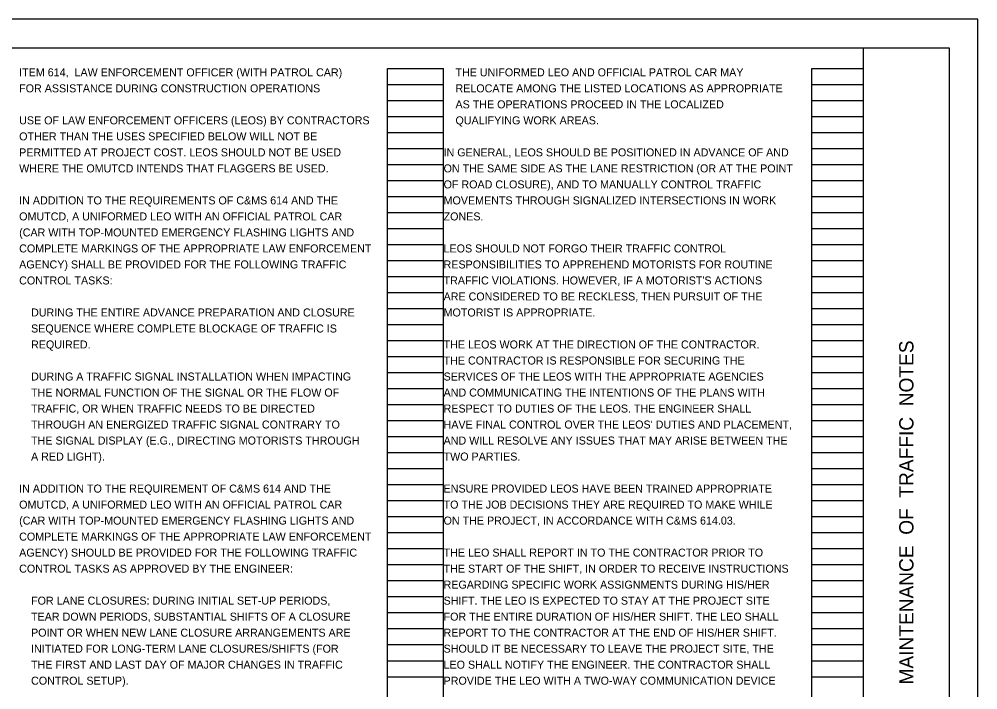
# Model space of a CAD drawing. Extents: x 0 to 34, y 0 to 22.
# Drawn here: x 17.24 to 34, y 10.27 to 22 of the extents above; entities that cross this region are included whole.
import ezdxf

# ---------------------------------------------------------------- set-up
doc = ezdxf.new("R2010")
doc.units = 0
for name, color, linetype in [('SH_Border', 7, 'Continuous'), ('SH_Cut_Line', 7, 'Continuous'), ('SH_Data', 7, 'Continuous'), ('SH_Text', 7, 'Continuous')]:
    doc.layers.add(name, color=color, linetype=linetype)

msp = doc.modelspace()

# ---------------------------------------------------------------- linework, layer by layer
at = {"layer": 'SH_Border'}
msp.add_line((32, 0.5), (32, 21.5), dxfattribs=at)
msp.add_lwpolyline([(1.5, 21.5), (33.5, 21.5), (33.5, 0.5), (1.5, 0.5)], close=True, dxfattribs=at)
at = {"layer": 'SH_Cut_Line'}
msp.add_lwpolyline([(0, 0), (34, 0), (34, 22), (0, 22)], close=True, dxfattribs=at)
at = {"layer": 'SH_Data'}
for p, q in [((23.68, 0.98), (23.68, 21.14)), ((23.68, 21.14), (24.66, 21.14)), ((24.66, 0.98), (24.66, 21.14)), ((31.1, 0.98), (31.1, 21.14)), ((31.1, 21.14), (32, 21.14)), ((32, 0.98), (32, 21.14)), ((23.68, 20.86), (24.66, 20.86)), ((31.1, 20.86), (32, 20.86)), ((23.68, 20.58), (24.66, 20.58)), ((31.1, 20.58), (32, 20.58)), ((23.68, 20.3), (24.66, 20.3)), ((31.1, 20.3), (32, 20.3)), ((23.68, 20.02), (24.66, 20.02)), ((31.1, 20.02), (32, 20.02)), ((23.68, 19.74), (24.66, 19.74)), ((31.1, 19.74), (32, 19.74)), ((23.68, 19.46), (24.66, 19.46)), ((31.1, 19.46), (32, 19.46)), ((23.68, 19.18), (24.66, 19.18)), ((31.1, 19.18), (32, 19.18)), ((23.68, 18.9), (24.66, 18.9)), ((31.1, 18.9), (32, 18.9)), ((23.68, 18.62), (24.66, 18.62)), ((31.1, 18.62), (32, 18.62)), ((23.68, 18.34), (24.66, 18.34)), ((31.1, 18.34), (32, 18.34)), ((23.68, 18.06), (24.66, 18.06)), ((31.1, 18.06), (32, 18.06)), ((23.68, 17.78), (24.66, 17.78)), ((31.1, 17.78), (32, 17.78)), ((23.68, 17.5), (24.66, 17.5)), ((31.1, 17.5), (32, 17.5)), ((23.68, 17.22), (24.66, 17.22)), ((31.1, 17.22), (32, 17.22)), ((23.68, 16.94), (24.66, 16.94)), ((31.1, 16.94), (32, 16.94)), ((23.68, 16.66), (24.66, 16.66)), ((31.1, 16.66), (32, 16.66)), ((23.68, 16.38), (24.66, 16.38)), ((31.1, 16.38), (32, 16.38)), ((23.68, 16.1), (24.66, 16.1)), ((31.1, 16.1), (32, 16.1)), ((23.68, 15.82), (24.66, 15.82)), ((31.1, 15.82), (32, 15.82)), ((23.68, 15.54), (24.66, 15.54)), ((31.1, 15.54), (32, 15.54)), ((23.68, 15.26), (24.66, 15.26)), ((31.1, 15.26), (32, 15.26)), ((23.68, 14.98), (24.66, 14.98)), ((31.1, 14.98), (32, 14.98)), ((23.68, 14.7), (24.66, 14.7)), ((31.1, 14.7), (32, 14.7)), ((23.68, 14.42), (24.66, 14.42)), ((31.1, 14.42), (32, 14.42)), ((23.68, 14.14), (24.66, 14.14)), ((31.1, 14.14), (32, 14.14)), ((23.68, 13.86), (24.66, 13.86)), ((31.1, 13.86), (32, 13.86)), ((23.68, 13.58), (24.66, 13.58)), ((31.1, 13.58), (32, 13.58)), ((23.68, 13.3), (24.66, 13.3)), ((31.1, 13.3), (32, 13.3)), ((23.68, 13.02), (24.66, 13.02)), ((31.1, 13.02), (32, 13.02)), ((23.68, 12.74), (24.66, 12.74)), ((31.1, 12.74), (32, 12.74)), ((23.68, 12.46), (24.66, 12.46)), ((31.1, 12.46), (32, 12.46)), ((23.68, 12.18), (24.66, 12.18)), ((31.1, 12.18), (32, 12.18)), ((23.68, 11.9), (24.66, 11.9)), ((31.1, 11.9), (32, 11.9)), ((23.68, 11.62), (24.66, 11.62)), ((31.1, 11.62), (32, 11.62)), ((23.68, 11.34), (24.66, 11.34)), ((31.1, 11.34), (32, 11.34)), ((23.68, 11.06), (24.66, 11.06)), ((31.1, 11.06), (32, 11.06)), ((23.68, 10.78), (24.66, 10.78)), ((31.1, 10.78), (32, 10.78)), ((23.68, 10.5), (24.66, 10.5)), ((31.1, 10.5), (32, 10.5))]:
    msp.add_line(p, q, dxfattribs=at)

# ---------------------------------------------------------------- texts
msp.add_text('MAINTENANCE  OF  TRAFFIC  NOTES', height=0.25, rotation=90, dxfattribs=at).set_placement((32.875, 10.363))
at = {"layer": 'SH_Text'}
for s, p in [('ITEM 614,  LAW ENFORCEMENT OFFICER (WITH PATROL CAR)', (17.24, 21)), ('    THE UNIFORMED LEO AND OFFICIAL PATROL CAR MAY', (24.66, 21)), ('FOR ASSISTANCE DURING CONSTRUCTION OPERATIONS', (17.24, 20.72)), ('    RELOCATE AMONG THE LISTED LOCATIONS AS APPROPRIATE', (24.66, 20.72)), ('    AS THE OPERATIONS PROCEED IN THE LOCALIZED', (24.66, 20.44)), ('USE OF LAW ENFORCEMENT OFFICERS (LEOS) BY CONTRACTORS', (17.24, 20.16)), ('    QUALIFYING WORK AREAS.', (24.66, 20.16)), ('OTHER THAN THE USES SPECIFIED BELOW WILL NOT BE', (17.24, 19.88)), ('PERMITTED AT PROJECT COST. LEOS SHOULD NOT BE USED', (17.24, 19.6)), ('IN GENERAL, LEOS SHOULD BE POSITIONED IN ADVANCE OF AND', (24.66, 19.6)), ('WHERE THE OMUTCD INTENDS THAT FLAGGERS BE USED.', (17.24, 19.32)), ('ON THE SAME SIDE AS THE LANE RESTRICTION (OR AT THE POINT', (24.66, 19.32)), ('OF ROAD CLOSURE), AND TO MANUALLY CONTROL TRAFFIC', (24.66, 19.04)), ('IN ADDITION TO THE REQUIREMENTS OF C&MS 614 AND THE', (17.24, 18.76)), ('MOVEMENTS THROUGH SIGNALIZED INTERSECTIONS IN WORK', (24.66, 18.76)), ('OMUTCD, A UNIFORMED LEO WITH AN OFFICIAL PATROL CAR', (17.24, 18.48)), ('ZONES.', (24.66, 18.48)), ('(CAR WITH TOP-MOUNTED EMERGENCY FLASHING LIGHTS AND', (17.24, 18.2)), ('COMPLETE MARKINGS OF THE APPROPRIATE LAW ENFORCEMENT', (17.24, 17.92)), ('LEOS SHOULD NOT FORGO THEIR TRAFFIC CONTROL', (24.66, 17.92)), ('AGENCY) SHALL BE PROVIDED FOR THE FOLLOWING TRAFFIC', (17.24, 17.64)), ('RESPONSIBILITIES TO APPREHEND MOTORISTS FOR ROUTINE', (24.66, 17.64)), ('CONTROL TASKS:', (17.24, 17.36)), ("TRAFFIC VIOLATIONS. HOWEVER, IF A MOTORIST'S ACTIONS", (24.66, 17.36)), ('ARE CONSIDERED TO BE RECKLESS, THEN PURSUIT OF THE', (24.66, 17.08)), ('    DURING THE ENTIRE ADVANCE PREPARATION AND CLOSURE', (17.24, 16.8)), ('MOTORIST IS APPROPRIATE.', (24.66, 16.8)), ('    SEQUENCE WHERE COMPLETE BLOCKAGE OF TRAFFIC IS', (17.24, 16.52)), ('    REQUIRED.', (17.24, 16.24)), ('THE LEOS WORK AT THE DIRECTION OF THE CONTRACTOR.', (24.66, 16.24)), ('THE CONTRACTOR IS RESPONSIBLE FOR SECURING THE', (24.66, 15.96)), ('    DURING A TRAFFIC SIGNAL INSTALLATION WHEN IMPACTING', (17.24, 15.68)), ('SERVICES OF THE LEOS WITH THE APPROPRIATE AGENCIES', (24.66, 15.68)), ('    THE NORMAL FUNCTION OF THE SIGNAL OR THE FLOW OF', (17.24, 15.4)), ('AND COMMUNICATING THE INTENTIONS OF THE PLANS WITH', (24.66, 15.4)), ('    TRAFFIC, OR WHEN TRAFFIC NEEDS TO BE DIRECTED', (17.24, 15.12)), ('RESPECT TO DUTIES OF THE LEOS. THE ENGINEER SHALL', (24.66, 15.12)), ('    THROUGH AN ENERGIZED TRAFFIC SIGNAL CONTRARY TO', (17.24, 14.84)), ("HAVE FINAL CONTROL OVER THE LEOS' DUTIES AND PLACEMENT,", (24.66, 14.84)), ('    THE SIGNAL DISPLAY (E.G., DIRECTING MOTORISTS THROUGH', (17.24, 14.56)), ('AND WILL RESOLVE ANY ISSUES THAT MAY ARISE BETWEEN THE', (24.66, 14.56)), ('    A RED LIGHT).', (17.24, 14.28)), ('TWO PARTIES.', (24.66, 14.28)), ('IN ADDITION TO THE REQUIREMENT OF C&MS 614 AND THE', (17.24, 13.72)), ('ENSURE PROVIDED LEOS HAVE BEEN TRAINED APPROPRIATE', (24.66, 13.72)), ('OMUTCD, A UNIFORMED LEO WITH AN OFFICIAL PATROL CAR', (17.24, 13.44)), ('TO THE JOB DECISIONS THEY ARE REQUIRED TO MAKE WHILE', (24.66, 13.44)), ('(CAR WITH TOP-MOUNTED EMERGENCY FLASHING LIGHTS AND', (17.24, 13.16)), ('ON THE PROJECT, IN ACCORDANCE WITH C&MS 614.03.', (24.66, 13.16)), ('COMPLETE MARKINGS OF THE APPROPRIATE LAW ENFORCEMENT', (17.24, 12.88)), ('AGENCY) SHOULD BE PROVIDED FOR THE FOLLOWING TRAFFIC', (17.24, 12.6)), ('THE LEO SHALL REPORT IN TO THE CONTRACTOR PRIOR TO', (24.66, 12.6)), ('CONTROL TASKS AS APPROVED BY THE ENGINEER:', (17.24, 12.32)), ('THE START OF THE SHIFT, IN ORDER TO RECEIVE INSTRUCTIONS', (24.66, 12.32)), ('REGARDING SPECIFIC WORK ASSIGNMENTS DURING HIS/HER', (24.66, 12.04)), ('    FOR LANE CLOSURES: DURING INITIAL SET-UP PERIODS,', (17.24, 11.76)), ('SHIFT. THE LEO IS EXPECTED TO STAY AT THE PROJECT SITE', (24.66, 11.76)), ('    TEAR DOWN PERIODS, SUBSTANTIAL SHIFTS OF A CLOSURE', (17.24, 11.48)), ('FOR THE ENTIRE DURATION OF HIS/HER SHIFT. THE LEO SHALL', (24.66, 11.48)), ('    POINT OR WHEN NEW LANE CLOSURE ARRANGEMENTS ARE', (17.24, 11.2)), ('REPORT TO THE CONTRACTOR AT THE END OF HIS/HER SHIFT.', (24.66, 11.2)), ('    INITIATED FOR LONG-TERM LANE CLOSURES/SHIFTS (FOR', (17.24, 10.92)), ('SHOULD IT BE NECESSARY TO LEAVE THE PROJECT SITE, THE', (24.66, 10.92)), ('    THE FIRST AND LAST DAY OF MAJOR CHANGES IN TRAFFIC', (17.24, 10.64)), ('LEO SHALL NOTIFY THE ENGINEER. THE CONTRACTOR SHALL', (24.66, 10.64)), ('    CONTROL SETUP).', (17.24, 10.36)), ('PROVIDE THE LEO WITH A TWO-WAY COMMUNICATION DEVICE', (24.66, 10.36))]:
    msp.add_text(s, height=0.14, dxfattribs=at).set_placement(p)

doc.saveas('drawing.dxf')
